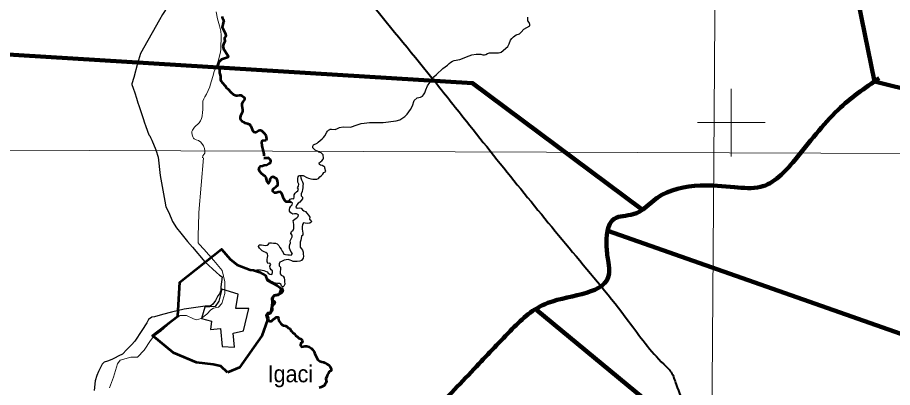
# Model space of a CAD drawing. Extents: x 553962 to 842807, y 8883888 to 9032388.
# Drawn here: x 753949 to 779754, y 8942188 to 8953102 of the extents above; entities that cross this region are included whole.
import ezdxf

# ---------------------------------------------------------------- set-up
doc = ezdxf.new("R2010")
doc.units = 0
doc.header["$LTSCALE"] = 20
for name, color, linetype, lineweight in [('1', 7, 'Continuous', 13), ('12', 7, 'Continuous', 25), ('14', 7, 'Continuous', 13), ('17', 7, 'Continuous', 53), ('2', 7, 'Continuous', 13), ('21', 7, 'Continuous', 25), ('24', 7, 'Continuous', 25), ('9', 7, 'Continuous', 90)]:
    doc.layers.add(name, color=color, linetype=linetype, lineweight=lineweight)
doc.layers.add('41', color=7, linetype='Continuous')

msp = doc.modelspace()

# ---------------------------------------------------------------- linework, layer by layer
at = {"layer": '1'}
msp.add_line((565315.27, 8949866.81), (791497.68, 8949052.23), dxfattribs=at)
msp.add_lwpolyline([(774987.06, 9020818), (774482.3, 8948876.02), (774053.56, 8890875.3)], dxfattribs=at)
at = {"layer": '12'}
msp.add_line((757384.55, 8951334.85), (757323.54, 8951149.2), dxfattribs=at)
for points in [[(758795.34, 8954919.79), (758763.74, 8954849.61), (758709.93, 8954774.52), (758538.4, 8954572.99), (758503.04, 8954502.62), (758483.99, 8954433.8), (758484.06, 8954352.36), (758508.26, 8954214.66), (758549.73, 8954085.3), (758582.85, 8954000.04), (758600.3, 8953935.19), (758599.47, 8953906.86), (758576.1, 8953802), (758547.25, 8953725.33), (758396.38, 8953446.47), (758226.24, 8953190.35), (758132.67, 8953037.95)], [(758132.67, 8953037.95), (757580.26, 8952039.84), (757484.88, 8951743.2), (757384.55, 8951334.85)], [(757323.54, 8951149.2), (757320.26, 8951125.53), (757364.24, 8951016.45), (757410.71, 8950880.99), (757454.68, 8950719.86), (757502.28, 8950586.31), (757524.75, 8950509.48), (757666.01, 8950096.69), (757688.03, 8950021.8), (757738.6, 8949883.52)], [(757738.6, 8949883.52), (757825.57, 8949645.69), (757854.17, 8949615.02), (757875.28, 8949559.36), (757912.71, 8949482.23), (758025.79, 8949198.11), (758100.61, 8948982.25)], [(758100.61, 8948982.25), (758153.12, 8948437.95), (758292.99, 8947683.77), (758328.03, 8947515.6), (758414.01, 8947347.34), (758520.04, 8947087.34), (758641.61, 8946898.64), (758763.29, 8946740.5), (758961.07, 8946495.61), (759108.18, 8946327.24), (759473.38, 8945893.57), (759813.98, 8945575.89), (759907.27, 8945497.25), (759983.74, 8945451.99)], [(759983.74, 8945451.99), (759944.45, 8945159.15), (759944.06, 8945052.18), (759908.02, 8944950.36), (759861.97, 8944894.41), (759785.03, 8944751.92), (759708.24, 8944650.18), (759662.24, 8944609.51), (759602.86, 8944587.98), (759488.41, 8944585.13)], [(759488.41, 8944585.13), (758867.12, 8944498.9), (758489.8, 8944407.9), (758229.73, 8944337.06), (757984.98, 8944276.38), (757913.6, 8944261.23), (757816.57, 8944195.19), (757760.15, 8944093.41), (757611.59, 8943869.54), (757411.75, 8943554.08), (757314.57, 8943447.28), (757171.42, 8943310), (757048.65, 8943172.69), (756936.39, 8943121.95), (756813.88, 8943055.95), (756729.62, 8943015), (756604.7, 8942969.74), (756502.68, 8942934.27), (756446.44, 8942878.34), (756333.56, 8942659.5), (756287.26, 8942537.32), (756240.85, 8942384.59), (756209.25, 8942104.47)]]:
    msp.add_lwpolyline(points, dxfattribs=at)
at = {"layer": '12', "lineweight": 40}
msp.add_spline([(761549.23, 8957020.39), (762383.1, 8955993.89), (763257, 8954902.9), (764214.4, 8953717.28), (766168.17, 8951324.42), (767086.6, 8950171.63), (770317.83, 8946184.23), (771971.01, 8944145.98), (773006.34, 8942876.25), (773223.42, 8942642.35), (773373.71, 8942274.8), (774008.27, 8940921.53), (774358.95, 8940136.3), (774475.84, 8939919.11), (774642.83, 8939785.46), (774893.31, 8939668.51), (775511.17, 8939484.73), (775928.64, 8939267.54), (776078.93, 8939184), (776379.51, 8938916.69), (776680.09, 8938749.62), (776830.38, 8938582.55), (777398.14, 8938348.65), (777899.1, 8938231.71), (778550.36, 8938482.31), (779134.82, 8938866.57), (779452.1, 8939250.83), (779568.99, 8939384.49), (779685.88, 8939351.07), (779852.87, 8939217.42), (780086.65, 8939217.42), (780604.32, 8939451.32), (781055.19, 8939618.39), (781439.26, 8939618.39), (781823.33, 8939518.14), (782090.52, 8939401.2), (782290.9, 8939367.78), (782524.69, 8939518.14), (782858.66, 8939618.39), (783192.64, 8939651.8), (783509.92, 8939818.87), (783910.69, 8940119.6), (784278.07, 8940336.79), (784625.22, 8940434.47)], degree=3, dxfattribs=at)
at = {"layer": '14'}
for points in [[(759812.4, 8953264.99), (759848.25, 8953062.83), (759909.86, 8952856.38), (759942.4, 8952701.71), (759952.88, 8952580.2), (759946.48, 8952160.2), (759939.28, 8952091.56), (759880.8, 8951841.75), (759807.49, 8951640.37), (759753.1, 8951507.26), (759709.28, 8951360.84)], [(759709.28, 8951360.84), (759631.97, 8951102.52), (759624.23, 8951061.46), (759522.6, 8950843.32), (759474.2, 8950762.91), (759445.53, 8950706.19), (759419.86, 8950637.93), (759411.13, 8950557.2), (759411.41, 8950380.26), (759406.77, 8950307.6), (759392.07, 8950195.03), (759374.29, 8950118.41), (759344.39, 8950053.95), (759304.03, 8949993.17), (759170.87, 8949865.14), (759105.38, 8949780.7), (759086.2, 8949743.52), (759087.4, 8949705.08), (759098.37, 8949641.22), (759121.33, 8949577.43), (759137.18, 8949545.11), (759155.86, 8949527.01), (759216.15, 8949497.08), (759288.52, 8949470.6), (759360.25, 8949422.03), (759430.58, 8949317.76), (759467.48, 8949241.1), (759477.52, 8949172.34), (759475.06, 8949104.01), (759414.58, 8949021.42), (759409.53, 8948961.27)], [(756657.81, 8942174.96), (756781.26, 8942495.66), (756894.76, 8942882.6), (756981.75, 8942989.42), (757287.77, 8943085.65), (757486.43, 8943080.19), (757685.89, 8943293.77), (757875.43, 8943578.69), (757972.67, 8943700.77), (758176.99, 8943848.13), (758371.23, 8944026.06), (758642.03, 8944244.61), (758749.25, 8944310.64), (758825.69, 8944315.59), (758932.65, 8944310.3), (759136.07, 8944213.14), (759232.75, 8944182.39), (759365.37, 8944228), (759528.83, 8944349.95), (759646.47, 8944477.09), (759733.28, 8944532.97), (759876.01, 8944558.17), (759978.29, 8944664.96), (760060.89, 8944960.27), (760062.16, 8945306.66), (759981.87, 8945637.93), (759743.55, 8945938.92), (759444.18, 8946265.49), (759307.2, 8946418.57), (759276.78, 8946459.37), (759277.14, 8946556.16), (759272.59, 8946703.9), (759283.68, 8946948.4), (759300.44, 8947350.8), (759434.44, 8948959.18)]]:
    msp.add_lwpolyline(points, dxfattribs=at)
at = {"layer": '17'}
msp.add_lwpolyline([(760138.79, 8942630.45), (759944.62, 8942815.89), (759723.97, 8942868.87), (759229.72, 8942921.85), (758550.13, 8943213.25), (757932.32, 8943725.41), (758673.69, 8944290.56), (758735.47, 8945297.22), (759962.27, 8946268.56), (760216.84, 8945977.59), (760428.66, 8945809.81), (760808.18, 8945659.7), (760905.26, 8945650.87), (761090.6, 8945589.05), (761267.12, 8945491.92), (761311.25, 8945350.63), (761602.51, 8945200.52), (761726.07, 8945112.21), (761664.29, 8944926.78), (761514.25, 8944900.28), (761452.47, 8944820.81), (761461.29, 8944697.19), (761443.64, 8944538.24), (761408.34, 8944379.29), (761284.77, 8944326.31), (761320.08, 8944185.03), (761152.39, 8943708.19), (760499.27, 8942781)], close=True, dxfattribs=at)
at = {"layer": '2'}
for p, q in [((775000, 8949000), (775000, 8951000)), ((774000, 8950000), (776000, 8950000))]:
    msp.add_line(p, q, dxfattribs=at)
at = {"layer": '21'}
msp.add_lwpolyline([(759971.81, 8945092.71), (759884.42, 8944736.97), (759777.91, 8944573.89), (759473.6, 8944557.94), (759374.39, 8944228.18), (759675.4, 8944141.8), (759642.3, 8943899.57), (759934.37, 8943928.72), (759980.73, 8943402.27), (760347.02, 8943377.84), (760309.61, 8943788.76), (760615.56, 8943855.88), (760776.05, 8944516.61), (760383.64, 8944516.26), (760460.44, 8944936.36)], close=True, dxfattribs=at)
at = {"layer": '24', "lineweight": 53}
for p, q in [((761210.88, 8948956.23), (761361.36, 8948961.1)), ((761361.36, 8948961.1), (761210.88, 8948956.23))]:
    msp.add_line(p, q, dxfattribs=at)
for points in [[(759993.34, 8953133.36), (759989.75, 8953090.2), (759995.19, 8953072.25), (760012.65, 8953041.9), (760030.45, 8952976.22), (760028.55, 8952967.68), (760010.51, 8952941.35), (760006.65, 8952900.19), (759980.51, 8952814.34), (760064.64, 8952661.37), (760083.73, 8952610.38), (760092.84, 8952563.45), (760088.52, 8952550.48), (760057.48, 8952502.29), (760057.12, 8952461.64), (760064.79, 8952410.99), (760063.13, 8952393.23), (760019.94, 8952313.42), (760004.69, 8952250.59), (760010.53, 8952223.05), (760028.2, 8952180.12), (760153.63, 8951982.2), (760158.82, 8951968.56), (760154.38, 8951934.47), (760142.6, 8951924.16), (760078.63, 8951897.76), (760029.02, 8951887.18), (759964.89, 8951861.72), (759906.29, 8951805.3), (759880.41, 8951769.16), (759863.63, 8951724.33), (759860.29, 8951690), (759879.36, 8951623.6), (759905.12, 8951564.95), (759908.9, 8951466.92), (759927.64, 8951412.04), (759938.89, 8951364.3), (759933.31, 8951303.02), (759936.83, 8951260.53), (759955.02, 8951224.68), (759979.83, 8951190.18), (760080.56, 8951077.74), (760114.71, 8951023.72), (760149.74, 8950995.83), (760252.78, 8950885.98), (760322.7, 8950833.38), (760365.98, 8950810.16), (760393.25, 8950802.78), (760433.69, 8950805.5), (760491.53, 8950815.97), (760531.56, 8950814.48), (760588.47, 8950783.69), (760628.39, 8950748.15), (760642.24, 8950730.66), (760646.39, 8950707.44), (760641.46, 8950688.14), (760625.43, 8950655), (760584.92, 8950601.98), (760566, 8950552.7), (760567.36, 8950502.14), (760585.59, 8950389.32), (760588.6, 8950335.21)], [(760588.6, 8950335.21), (760579.41, 8950302.59), (760526.16, 8950197.77), (760517.92, 8950150.88), (760518.58, 8950115), (760524.79, 8950096.2), (760560.23, 8950052.45), (760573.58, 8950045.6), (760600.39, 8950021.63), (760652.62, 8949994.67), (760735.25, 8949978.41), (760796.26, 8949944.69), (760827, 8949897.83), (760870.53, 8949794.41), (760894.36, 8949756.4), (760917.93, 8949733.04), (760957.72, 8949723.44), (760983.85, 8949722.97)], [(760983.85, 8949722.97), (761052.14, 8949768.54), (761052.14, 8949768.54), (761093.16, 8949782.45), (761118.68, 8949782.48), (761143.02, 8949765.48), (761222.46, 8949692.04), (761270.08, 8949631.36), (761287.68, 8949574.99), (761290.9, 8949523.61), (761283.12, 8949497.5), (761268.69, 8949478.82), (761253.36, 8949469.91), (761168.05, 8949460.94), (761157.1, 8949449.26), (761149.42, 8949429.22), (761159.36, 8949316.58), (761205.57, 8949123.6), (761214.31, 8949072.63), (761216.86, 8949017.89)], [(762015.2, 8947644.99), (761987.79, 8947662.21), (761936.94, 8947662.53), (761870.86, 8947668.03), (761835.54, 8947709), (761800.22, 8947749.96), (761780.23, 8947801.02), (761760.28, 8947857.17), (761740.32, 8947913.33), (761694.86, 8947959.45), (761638.89, 8947954.7), (761577.72, 8947934.71), (761526.87, 8947935.03), (761476.26, 8947971), (761476.64, 8948027.02), (761517.64, 8948072.61), (761568.74, 8948107.94), (761625.03, 8948158.52), (761625.45, 8948219.64), (761620.82, 8948285.89), (761600.87, 8948342.04), (761489.37, 8948398.76), (761433.29, 8948378.73), (761387.24, 8948338.27), (761386.82, 8948277.16), (761350.73, 8948206.07), (761310.43, 8948262.35), (761295.63, 8948328.66), (761280.73, 8948379.68), (761255.61, 8948425.68), (761204.93, 8948451.46), (761149.34, 8948502.74), (761098.91, 8948564.18), (761068.71, 8948610.21), (761084.42, 8948676.32), (761120.3, 8948716.84), (761176.31, 8948726.68), (761227.27, 8948741.65), (761298.57, 8948756.48), (761359.84, 8948791.75), (761405.79, 8948816.94), (761421.43, 8948872.86), (761391.27, 8948923.99), (761361.36, 8948961.1)], [(761737.34, 8945134.74), (761755.23, 8945087.54), (761775.15, 8945026.29), (761739.23, 8944980.68), (761683.11, 8944955.57), (761637.02, 8944910.02), (761575.96, 8944905.32), (761514.82, 8944890.43), (761478.97, 8944855), (761468.42, 8944799.03), (761468.03, 8944743), (761518.82, 8944732.49), (761533.73, 8944681.46), (761513.07, 8944635.74), (761467.12, 8944610.57), (761451.51, 8944559.73), (761461.33, 8944508.73), (761455.9, 8944457.83), (761425.03, 8944407.09), (761374, 8944381.94), (761323.1, 8944377.18), (761302.44, 8944331.46), (761327.49, 8944275.27), (761337.28, 8944219.18), (761347.06, 8944163.08), (761392.7, 8944142.41), (761443.59, 8944147.18), (761489.68, 8944192.73), (761535.66, 8944223), (761576.6, 8944258.39), (761632.58, 8944263.13), (761642.4, 8944212.12), (761657.27, 8944156), (761687.51, 8944115.05), (761717.74, 8944074.11), (761753.1, 8944038.22), (761798.73, 8944017.56), (761849.52, 8944007.04), (761895.15, 8943986.37), (761930.51, 8943950.49), (761981.23, 8943929.79), (762001.26, 8943883.82), (762036.58, 8943842.84), (762071.9, 8943801.86), (762117.47, 8943771.01), (762157.73, 8943709.62), (762203.3, 8943678.77), (762243.74, 8943642.85), (762304.67, 8943627.18), (762339.99, 8943586.2), (762349.77, 8943530.1), (762308.84, 8943494.71), (762293.13, 8943428.59), (762323.36, 8943387.65), (762374.29, 8943397.51), (762425.22, 8943407.37), (762486.25, 8943406.98), (762552.23, 8943386.18), (762613.02, 8943350.13), (762653.43, 8943309.12), (762693.66, 8943242.64), (762713.58, 8943181.39), (762748.8, 8943125.13), (762773.81, 8943063.84), (762803.94, 8943007.62)], [(762803.94, 8943007.62), (762864.69, 8942966.48), (762920.46, 8942940.65), (762971.28, 8942935.23), (763016.92, 8942914.56), (763077.7, 8942878.52), (763133.4, 8942842.5), (763173.81, 8942801.49), (763203.94, 8942745.27), (763203.52, 8942684.14), (763147.4, 8942659.03), (763116.57, 8942613.39), (763095.91, 8942567.67), (763070.1, 8942511.81), (763044.21, 8942445.75), (763054.03, 8942394.75), (763058.77, 8942343.78), (763022.89, 8942303.26), (763002.16, 8942247.36), (762946, 8942217.16), (762900.09, 8942197.08), (762849.09, 8942177.03)]]:
    msp.add_lwpolyline(points, dxfattribs=at)
at = {"layer": '24'}
for points in [[(759993.34, 8953133.36), (759989.75, 8953090.2), (759995.19, 8953072.25), (760012.65, 8953041.9), (760030.45, 8952976.22), (760028.55, 8952967.68), (760010.51, 8952941.35), (760006.65, 8952900.19), (759980.51, 8952814.34), (760064.64, 8952661.37), (760083.73, 8952610.38), (760092.84, 8952563.45), (760088.52, 8952550.48), (760057.48, 8952502.29), (760057.12, 8952461.64), (760064.79, 8952410.99), (760063.13, 8952393.23), (760019.94, 8952313.42), (760004.69, 8952250.59), (760010.53, 8952223.05), (760028.2, 8952180.12), (760153.63, 8951982.2), (760158.82, 8951968.56), (760154.38, 8951934.47), (760142.6, 8951924.16), (760078.63, 8951897.76), (760029.02, 8951887.18), (759964.89, 8951861.72), (759906.29, 8951805.3), (759880.41, 8951769.16), (759863.63, 8951724.33), (759860.29, 8951690), (759879.36, 8951623.6), (759905.12, 8951564.95), (759908.9, 8951466.92), (759927.64, 8951412.04), (759938.89, 8951364.3), (759933.31, 8951303.02), (759936.83, 8951260.53), (759955.02, 8951224.68), (759979.83, 8951190.18), (760080.56, 8951077.74), (760114.71, 8951023.72), (760149.74, 8950995.83), (760252.78, 8950885.98), (760322.7, 8950833.38), (760365.98, 8950810.16), (760393.25, 8950802.78), (760433.69, 8950805.5), (760491.53, 8950815.97), (760531.56, 8950814.48), (760588.47, 8950783.69), (760628.39, 8950748.15), (760642.24, 8950730.66), (760646.39, 8950707.44), (760641.46, 8950688.14), (760625.43, 8950655), (760584.92, 8950601.98), (760566, 8950552.7), (760567.36, 8950502.14), (760585.59, 8950389.32), (760588.6, 8950335.21)], [(768186.04, 8952066.58), (768216.91, 8952076.99), (768276.79, 8952125.59), (768349.48, 8952201.81), (768404.97, 8952249.01), (768448.64, 8952322.15), (768492.45, 8952435.55), (768528.1, 8952482.7), (768574.23, 8952530.78), (768613.28, 8952565.26), (768657.08, 8952591.39), (768749.73, 8952621.24), (768800.65, 8952669.18), (768878.11, 8952754.59), (768973.77, 8952803.21), (769059.97, 8952859.16), (769063.13, 8952875.69), (769060.02, 8952894.52), (769035.21, 8952954.28), (768999.56, 8953006.29), (768995.95, 8953049.42), (769003.83, 8953113.71)], [(762654.72, 8949294.45), (762656.69, 8949306.75), (762679.08, 8949343.58), (762788.71, 8949399.1), (762821.06, 8949420.09), (762935.32, 8949520.63), (762977.05, 8949566.55), (763011.06, 8949614.1), (763074.55, 8949715.94), (763089.37, 8949752.7), (763125.89, 8949775.51), (763156, 8949801.13), (763169.28, 8949805.24), (763212.89, 8949808.09), (763314.74, 8949796.06), (763389.39, 8949825.79), (763440.67, 8949858.61), (763555.17, 8949879.53), (763767.25, 8949868.88), (763967.13, 8949935.98), (764029.14, 8949960.5), (764080.25, 8949974.48), (764174.71, 8949982.81), (764331.56, 8950003.86), (764575.51, 8950000.01), (764735.93, 8950008.25), (765114.31, 8950054.99), (765220.67, 8950084.28), (765370.31, 8950178.22), (765443.68, 8950253.28), (765542.93, 8950392.96), (765598.59, 8950494.86), (765646.77, 8950651.07), (765735.25, 8950727.64), (765832.84, 8950754.03), (765891.77, 8950782.37), (765926.86, 8950823), (765961.13, 8950880.3), (765989.89, 8950971.36), (766040.94, 8951087.46), (766108.07, 8951189.63), (766159.25, 8951254.64), (766195.33, 8951316.51), (766224.57, 8951348.08), (766309.18, 8951420.9), (766494.81, 8951595.84), (766626.93, 8951699.86), (766678.78, 8951749.21), (766729.58, 8951787.42), (766780.63, 8951816.89), (766824.22, 8951832.03), (766991.89, 8951866.21), (767075.74, 8951890.48), (767194.01, 8951942.71), (767344.78, 8951998.87), (767476.09, 8952017.34), (767610.5, 8952017.18), (767669.11, 8952003.52), (767722.66, 8952005.15), (767758.46, 8952013.42), (767805.77, 8952043.21), (767869.44, 8952058.57), (768139.32, 8952060.83), (768186.04, 8952066.58), (768186.04, 8952066.58)], [(760588.6, 8950335.21), (760579.41, 8950302.59), (760526.16, 8950197.77), (760517.92, 8950150.88), (760518.58, 8950115), (760524.79, 8950096.2), (760560.23, 8950052.45), (760573.58, 8950045.6), (760600.39, 8950021.63), (760652.62, 8949994.67), (760735.25, 8949978.41), (760796.26, 8949944.69), (760827, 8949897.83), (760870.53, 8949794.41), (760894.36, 8949756.4), (760917.93, 8949733.04), (760957.72, 8949723.44), (760983.85, 8949722.97)], [(760983.85, 8949722.97), (761052.14, 8949768.54), (761052.14, 8949768.54), (761093.16, 8949782.45), (761118.68, 8949782.48), (761143.02, 8949765.48), (761222.46, 8949692.04), (761270.08, 8949631.36), (761287.68, 8949574.99), (761290.9, 8949523.61), (761283.12, 8949497.5), (761268.69, 8949478.82), (761253.36, 8949469.91), (761168.05, 8949460.94), (761157.1, 8949449.26), (761149.42, 8949429.22), (761159.36, 8949316.58), (761205.57, 8949123.6), (761214.31, 8949072.63), (761216.86, 8949017.89)], [(762975.51, 8948950.63), (762963.44, 8949055.97), (762906.02, 8949108.64), (762836.57, 8949131.35), (762820.09, 8949147.22), (762725, 8949191.46), (762705.85, 8949206.55), (762661.66, 8949253.27), (762654.72, 8949294.45)], [(763037.65, 8948563.39), (763015.99, 8948657.67), (763008.88, 8948685.85), (762983.87, 8948709.24), (762933.43, 8948733.08), (762882.7, 8948741.63), (762855.1, 8948762.52), (762848.42, 8948813.64), (762871.79, 8948838.73), (762897.51, 8948853.58), (762923.33, 8948873.53), (762959.89, 8948923.89), (762975.63, 8948949.11), (762975.51, 8948950.63)], [(762274.38, 8948440.87), (762371.25, 8948443.43), (762477.51, 8948379.59), (762533.35, 8948363.96), (762599.32, 8948343.18), (762655.22, 8948337.74), (762711.16, 8948337.39), (762777.27, 8948336.98), (762828.27, 8948357.03), (762869.27, 8948402.62), (762910.23, 8948443.11), (762951.2, 8948483.6), (762987.14, 8948534.31), (763037.65, 8948563.4)], [(762294.58, 8948431.64), (762309.42, 8948370.42), (762329.34, 8948309.17), (762354.39, 8948252.97), (762369.26, 8948196.85), (762368.91, 8948145.91), (762368.45, 8948079.69), (762352.81, 8948023.76), (762342.25, 8947967.8), (762311.28, 8947901.77), (762310.86, 8947840.65), (762351.3, 8947804.73), (762350.92, 8947748.7), (762315, 8947703.09), (762274, 8947657.51), (762222.9, 8947622.18), (762186.94, 8947571.47), (762156.01, 8947510.54), (762201.54, 8947474.59), (762252.5, 8947489.55), (762313.43, 8947473.88), (762353.83, 8947432.87), (762394.28, 8947396.95), (762439.91, 8947376.28), (762480.28, 8947330.18), (762535.84, 8947273.79), (762565.94, 8947212.47), (762560.47, 8947156.47), (762600.94, 8947125.65), (762620.97, 8947079.68), (762569.8, 8947034.16), (762508.73, 8947029.46), (762437.56, 8947035.01), (762381.65, 8947040.46), (762350.86, 8946999.91), (762340.19, 8946928.66), (762339.74, 8946862.45), (762354.54, 8946796.13), (762364.33, 8946740.04), (762368.99, 8946678.88), (762328.1, 8946648.58), (762312.42, 8946587.55), (762306.98, 8946536.65), (762286.18, 8946470.56), (762285.66, 8946394.16), (762285.17, 8946322.85), (762320.49, 8946281.87), (762350.72, 8946240.92), (762375.73, 8946179.64), (762375.35, 8946123.61), (762379.98, 8946057.36), (762374.51, 8946001.36), (762328.28, 8945935.44), (762272.19, 8945915.42), (762195.8, 8945900.63), (762134.77, 8945901.02), (762083.91, 8945901.35), (762038.31, 8945927.11), (761992.68, 8945947.78), (761931.75, 8945963.45), (761875.77, 8945958.72), (761809.55, 8945943.86), (761738.06, 8945903.57), (761681.98, 8945883.55), (761666.37, 8945832.71), (761665.98, 8945776.68), (761706.43, 8945740.77), (761694.89, 8945542.18), (761725.12, 8945501.23), (761781.45, 8945468.27), (761814.44, 8945424.23), (761825.44, 8945358.16), (761825.44, 8945314.12), (761836.44, 8945237.05), (761803.44, 8945181.99), (761788.89, 8945159.54), (761738.14, 8945175.14), (761723.23, 8945226.18), (761672.58, 8945257.07), (761621.72, 8945257.39), (761555.64, 8945262.91), (761504.89, 8945278.52), (761459.29, 8945304.28), (761403.55, 8945335.2), (761347.89, 8945376.31), (761312.57, 8945417.29), (761292.54, 8945463.26), (761247.08, 8945509.39), (761176.09, 8945540.41), (761125.37, 8945561.11), (761069.6, 8945586.94), (761023.96, 8945607.61), (761009.05, 8945658.64), (761059.91, 8945658.32), (761110.77, 8945657.99), (761161.56, 8945647.48), (761212.39, 8945642.06), (761263.11, 8945621.36), (761308.71, 8945595.59), (761344.06, 8945559.71), (761389.63, 8945528.86)], [(761389.63, 8945528.86), (761450.62, 8945523.37), (761471.35, 8945579.27), (761466.62, 8945630.24), (761426.14, 8945661.06), (761401.06, 8945712.16), (761391.27, 8945768.26), (761422.14, 8945819), (761391.9, 8945859.94), (761330.8, 8945850.15), (761315.89, 8945901.18), (761316.35, 8945967.4), (761321.78, 8946018.3), (761332.34, 8946074.27), (761317.5, 8946135.49), (761271.98, 8946171.44), (761221.26, 8946192.14), (761165.52, 8946223.06), (761125.04, 8946253.88), (761089.72, 8946294.86), (761059.59, 8946351.08), (761080.25, 8946396.8), (761141.28, 8946396.4), (761207.36, 8946390.89), (761263.24, 8946380.34), (761314.13, 8946385.11), (761349.98, 8946420.53), (761385.83, 8946455.96), (761441.77, 8946455.6), (761497.68, 8946450.15), (761558.72, 8946449.76), (761609.44, 8946429.06), (761659.94, 8946377.8), (761690.08, 8946321.57), (761725.33, 8946270.41), (761750.37, 8946214.21), (761785.69, 8946173.24), (761805.69, 8946122.17), (761856.44, 8946106.56), (761917.44, 8946101.08), (761968.3, 8946100.75), (762019.09, 8946090.24), (762055, 8946135.85), (762009.65, 8946197.27), (761994.74, 8946248.3), (761974.75, 8946299.37), (761970.05, 8946355.43), (761980.57, 8946406.3), (761996.18, 8946457.14), (761991.51, 8946518.3), (762022.41, 8946574.13), (762053.35, 8946635.06), (762048.61, 8946686.03), (762013.33, 8946732.1), (762029.01, 8946793.12), (762075.06, 8946833.58), (762095.72, 8946879.29), (762096.17, 8946945.51), (762096.52, 8946996.45), (762086.77, 8947057.63), (762082.07, 8947113.7), (762138.33, 8947159.18), (762189.44, 8947194.51), (762225.28, 8947229.94), (762235.81, 8947280.81), (762174.98, 8947311.76), (762119, 8947307.03), (762068.11, 8947302.26), (762007.32, 8947338.31), (761966.99, 8947389.5), (761967.34, 8947440.44), (761977.86, 8947491.31), (762013.78, 8947536.93), (762049.66, 8947577.45), (762060.21, 8947633.41), (761999.29, 8947649.08), (761964.07, 8947705.34), (761994.87, 8947745.89), (762045.83, 8947760.85), (762096.66, 8947755.43), (762107.25, 8947816.49), (762107.63, 8947872.52), (762133.41, 8947923.29), (762174.35, 8947958.69), (762220.33, 8947988.95), (762235.94, 8948039.79), (762205.7, 8948080.74), (762231.48, 8948131.51), (762247.13, 8948187.44), (762211.95, 8948248.79), (762212.3, 8948299.73), (762212.65, 8948350.67), (762226.37, 8948402.43), (762246.64, 8948432.33), (762274.38, 8948440.87), (762294.58, 8948431.64)]]:
    msp.add_lwpolyline(points, dxfattribs=at)
at = {"layer": '9'}
for p, q in [((779222.16, 8951211.15), (787994.96, 8949076.72)), ((782526.08, 8942878.47), (771355.16, 8946811.13))]:
    msp.add_line(p, q, dxfattribs=at)
for points in [[(779222.16, 8951211.15), (778550.56, 8954494.56), (777527.61, 8956664.64), (776378.14, 8958732.78), (766764.89, 8967647.48)], [(750519.5, 8951321.17), (753181.56, 8952045.06), (767370.95, 8951165.78), (772338.66, 8947456.49)], [(769262.28, 8944467.07), (774822.07, 8939873.46), (781306.63, 8936216.87)]]:
    msp.add_lwpolyline(points, dxfattribs=at)
msp.add_spline([(779358.35, 8951316.51), (778152.02, 8950383.18), (776870.48, 8948892.99), (775858.22, 8948102.75), (775096.9, 8948098.34), (774081.62, 8948143.06), (772814.04, 8947781.48), (772105.21, 8947296.63), (771547.36, 8947166.89), (771321.98, 8946330.6), (771374.38, 8945875.46), (771395.14, 8945546.09), (769593.34, 8944681.55), (768541.64, 8943918.78), (767488.26, 8942812.19), (766189.18, 8941452.32), (765366.7, 8940768.99), (764084.45, 8940646.23), (763321.48, 8941097.25), (762890.25, 8941044.15), (762866.33, 8940639.17), (762461.94, 8940181.38), (761397.37, 8939820.98), (760940.22, 8939919.54), (760874.96, 8939930.16)], degree=3, dxfattribs=at)

# ---------------------------------------------------------------- texts
at = {"layer": '41', "width": 0.95}
msp.add_text('Igaci', height=500, dxfattribs=at).set_placement((761325.03, 8942341.63))

doc.saveas('drawing.dxf')
